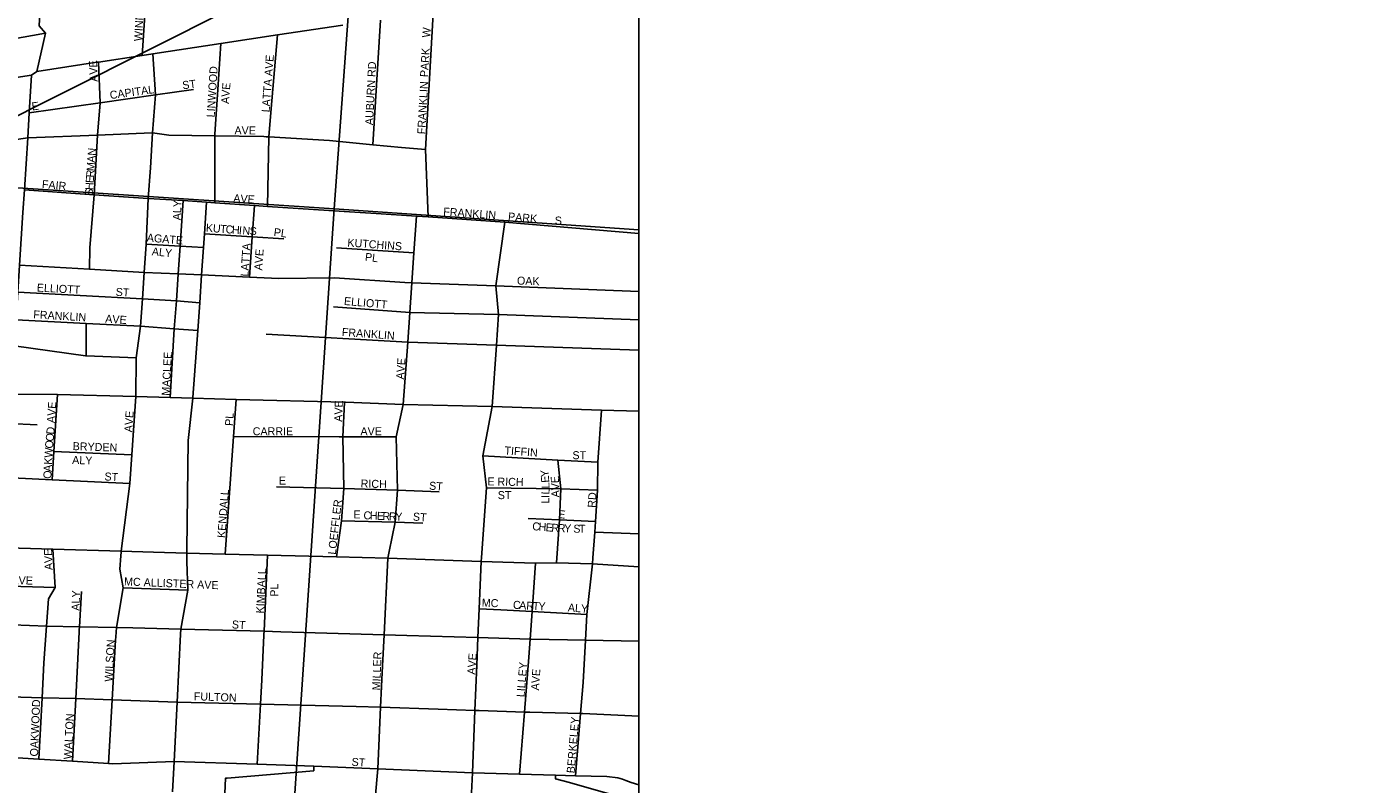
# Model space of a CAD drawing. Extents: x 0 to 34, y -6.2 to 22.
# Drawn here: x 8.351 to 9.927, y 17.461 to 18.357 of the extents above; entities that cross this region are included whole.
import ezdxf

# ---------------------------------------------------------------- set-up
doc = ezdxf.new("R2010")
doc.units = 0
for name, color, linetype in [('GM_X_City_Street', 7, 'Continuous'), ('GM_X_City_Street_Text', 7, 'Continuous'), ('GM_X_Corporation', 7, 'Continuous'), ('GM_X_Interchange_Ramps', 7, 'Continuous'), ('GM_X_Section', 7, 'Continuous'), ('GM_X_US_Route', 7, 'Continuous'), ('SH_Data', 7, 'Continuous')]:
    doc.layers.add(name, color=color, linetype=linetype)

msp = doc.modelspace()

# ---------------------------------------------------------------- linework, layer by layer
at = {"layer": 'GM_X_City_Street'}
for points in [[(8.3631, 18.3042), (8.3734, 18.3494), (8.3659, 18.3582), (8.3692, 18.4197), (8.3729, 18.4904), (8.373, 18.4917)], [(8.4879, 18.3231), (8.4941, 18.4189), (8.4953, 18.4367), (8.4955, 18.4396), (8.4958, 18.4443)], [(8.7608, 18.2175), (8.7699, 18.3648)], [(8.8262, 18.1321), (8.8232, 18.2118), (8.8321, 18.3727)], [(8.2861, 18.3332), (8.3316, 18.342), (8.3734, 18.3494)], [(8.6363, 18.1446), (8.6379, 18.2267), (8.64, 18.2557), (8.6479, 18.3474)], [(8.5737, 18.1488), (8.5737, 18.2279), (8.5738, 18.23), (8.5773, 18.2828), (8.5808, 18.3373)], [(8.4254, 18.0704), (8.426, 18.0957), (8.4311, 18.1584), (8.4352, 18.2289), (8.438, 18.2671), (8.4363, 18.3152)], [(8.4626, 17.7314), (8.463, 17.7356), (8.4631, 17.7367), (8.4734, 17.8167), (8.4756, 17.8508), (8.4805, 17.9197), (8.4806, 17.9653), (8.4859, 18.0028), (8.4882, 18.0351), (8.4903, 18.0666), (8.4925, 18.1), (8.4951, 18.1541), (8.4978, 18.19), (8.5002, 18.2315), (8.5036, 18.2765), (8.5004, 18.325)], [(8.3032, 17.5063), (8.3063, 17.5653), (8.3138, 17.6507), (8.3169, 17.6959), (8.3155, 17.7411), (8.3178, 17.7755), (8.3262, 17.8238), (8.3301, 17.8877), (8.328, 17.9227), (8.3364, 17.9796), (8.3387, 18.0105), (8.3408, 18.043), (8.3428, 18.0751), (8.3466, 18.1374), (8.3485, 18.1642), (8.3525, 18.2258), (8.3542, 18.2554), (8.3569, 18.2998)], [(8.3542, 18.2554), (8.438, 18.2671), (8.5036, 18.2765), (8.5487, 18.2829)], [(8.2737, 18.2141), (8.2764, 18.2145), (8.3525, 18.2258), (8.4352, 18.2289), (8.4992, 18.2314)], [(8.4992, 18.2314), (8.5002, 18.2315), (8.5195, 18.2287), (8.5737, 18.2279), (8.6317, 18.2271), (8.6347, 18.2269), (8.6368, 18.2268)], [(8.6368, 18.2268), (8.6379, 18.2267), (8.7096, 18.2226), (8.7608, 18.2175), (8.7946, 18.2141), (8.8232, 18.2118)], [(8.3485, 18.1642), (8.4311, 18.1584), (8.4951, 18.1541), (8.5364, 18.1514), (8.564, 18.1494), (8.5737, 18.1488), (8.6209, 18.1457), (8.6363, 18.1446), (8.7269, 18.1387), (8.7646, 18.1362), (8.8125, 18.1331)], [(8.5212, 17.9186), (8.5259, 17.9997), (8.5284, 18.0328), (8.5306, 18.0647), (8.5327, 18.0975), (8.5364, 18.1514)], [(8.548, 17.9186), (8.5537, 17.9978), (8.556, 18.0306), (8.5582, 18.0635), (8.5603, 18.0958), (8.5617, 18.1123), (8.564, 18.1494)], [(8.6148, 18.0607), (8.618, 18.1086), (8.6209, 18.1457)], [(8.8125, 18.1331), (8.8095, 18.0897), (8.807, 18.0542), (8.8046, 18.0191), (8.8022, 17.9841), (8.7969, 17.9105), (8.7886, 17.8719), (8.79, 17.8088), (8.7874, 17.7713), (8.7802, 17.7366)], [(8.8125, 18.1331), (8.8262, 18.1321), (8.9169, 18.1261), (9.0755, 18.1125)], [(8.8894, 17.7294), (8.8953, 17.8118), (8.8912, 17.8495), (8.9021, 17.9079), (8.9071, 17.9804), (8.9095, 18.0166), (8.9065, 18.0507), (8.9169, 18.1261)], [(8.5617, 18.1123), (8.618, 18.1086), (8.6556, 18.1064)], [(8.4925, 18.1), (8.5327, 18.0975), (8.5603, 18.0958)], [(8.7178, 18.0957), (8.8095, 18.0897)], [(7.7063, 18.0804), (7.764, 18.0773), (7.8241, 18.0739), (7.8921, 18.0686), (7.953, 18.0647), (8.0271, 18.0618), (8.0864, 18.0573), (8.1478, 18.0538), (8.2018, 18.0505), (8.2656, 18.0473), (8.3408, 18.043), (8.4882, 18.0351), (8.5284, 18.0328), (8.556, 18.0306)], [(8.3428, 18.0751), (8.4254, 18.0704), (8.4903, 18.0666), (8.5306, 18.0647), (8.5582, 18.0635), (8.6148, 18.0607), (8.6497, 18.0593), (8.7155, 18.0601), (8.7986, 18.0547)], [(8.7986, 18.0547), (8.807, 18.0542), (8.9065, 18.0507)], [(8.9065, 18.0507), (9.0755, 18.0438)], [(7.7622, 18.0447), (7.822, 18.041), (7.8901, 18.0366), (7.9508, 18.0329), (8.0249, 18.0288), (8.0839, 18.0254), (8.1454, 18.0219), (8.1993, 18.0186), (8.2634, 18.0144), (8.3387, 18.0105), (8.4217, 18.0062), (8.4859, 18.0028), (8.5259, 17.9997), (8.5537, 17.9978)], [(8.7142, 18.0259), (8.8046, 18.0191), (8.9095, 18.0166), (9.0755, 18.0105)], [(8.4215, 17.968), (8.4217, 18.0062)], [(8.2531, 17.9839), (8.2614, 17.9836), (8.3364, 17.9796), (8.4207, 17.968), (8.421, 17.968)], [(8.6346, 17.9935), (8.8022, 17.9841), (8.9071, 17.9804), (9.0755, 17.9746)], [(8.421, 17.968), (8.4215, 17.968), (8.4806, 17.9653)], [(8.328, 17.9227), (8.3878, 17.922), (8.4805, 17.9197), (8.5212, 17.9186), (8.548, 17.9178), (8.599, 17.9163), (8.7275, 17.913), (8.7285, 17.913), (8.7969, 17.9105), (8.9021, 17.9079), (9.0315, 17.9037), (9.0755, 17.9025)], [(8.3814, 17.8212), (8.3835, 17.8549), (8.3878, 17.922)], [(7.6611, 17.906), (7.8013, 17.9023), (7.8366, 17.901), (7.9008, 17.8997), (7.9745, 17.8937), (8.0127, 17.8935), (8.0535, 17.8924), (8.1008, 17.8908), (8.148, 17.89), (8.1893, 17.889), (8.255, 17.8894), (8.3301, 17.8877), (8.3636, 17.8861)], [(8.5409, 17.7377), (8.5409, 17.7387), (8.5424, 17.8679), (8.548, 17.9178), (8.548, 17.9186)], [(8.5859, 17.7333), (8.5958, 17.8724), (8.599, 17.9163)], [(8.7177, 17.73), (8.7238, 17.7728), (8.7266, 17.8109), (8.7253, 17.872), (8.7275, 17.913)], [(9.0214, 17.729), (9.0235, 17.7595), (9.0243, 17.7721), (9.0269, 17.8091), (9.0272, 17.8421), (9.0315, 17.9037)], [(8.5958, 17.8724), (8.7211, 17.8721)], [(8.7211, 17.8721), (8.7211, 17.8721), (8.7253, 17.872), (8.7886, 17.8719)], [(8.3835, 17.8549), (8.4756, 17.8508)], [(8.8912, 17.8495), (8.9797, 17.8444), (9.0272, 17.8421)], [(8.9782, 17.723), (8.9816, 17.7739), (8.9833, 17.8106), (8.9797, 17.8444)], [(8.0499, 17.835), (8.0968, 17.8333), (8.1443, 17.8315), (8.1838, 17.83), (8.2508, 17.8274), (8.3262, 17.8238), (8.3814, 17.8212), (8.4734, 17.8167)], [(8.6467, 17.8131), (8.7266, 17.8109), (8.79, 17.8088), (8.8393, 17.8071)], [(8.8953, 17.8118), (8.9833, 17.8106), (9.0269, 17.8091)], [(8.7238, 17.7728), (8.7874, 17.7713)], [(8.7874, 17.7713), (8.8202, 17.7701)], [(8.9448, 17.7755), (8.9816, 17.7739)], [(8.9816, 17.7739), (9.0243, 17.7721)], [(9.0235, 17.7595), (9.0755, 17.7574)], [(8.3155, 17.7411), (8.3822, 17.7391), (8.4631, 17.7367), (8.5014, 17.7356), (8.5408, 17.7344), (8.5859, 17.7333), (8.6363, 17.7321), (8.7177, 17.73), (8.7785, 17.7285), (8.8891, 17.7247), (8.9534, 17.7225), (8.9782, 17.723), (9.0209, 17.7217), (9.0755, 17.7184)], [(8.3654, 17.4909), (8.3694, 17.5636), (8.3716, 17.6048), (8.3748, 17.648), (8.3771, 17.6803), (8.3849, 17.6939), (8.3822, 17.7391)], [(8.4565, 17.6316), (8.4567, 17.6356), (8.4574, 17.6465), (8.4654, 17.6935), (8.4614, 17.7157), (8.4626, 17.7314)], [(8.5236, 17.4524), (8.5259, 17.4883), (8.5293, 17.5584), (8.5331, 17.6386), (8.5336, 17.6446), (8.5419, 17.6908), (8.5407, 17.7248), (8.5408, 17.7344), (8.5409, 17.7377)], [(8.6319, 17.6388), (8.6321, 17.6421), (8.6363, 17.7321)], [(8.7802, 17.7366), (8.7785, 17.7285), (8.7742, 17.6381), (8.7724, 17.6013), (8.7701, 17.5523), (8.7666, 17.4793), (8.7638, 17.4443), (8.7611, 17.4091), (8.7547, 17.3346), (8.751, 17.2441), (8.7455, 17.1496)], [(8.8578, 17.1414), (8.865, 17.2366), (8.8676, 17.3283), (8.8742, 17.4053), (8.8773, 17.443), (8.8787, 17.4747), (8.8817, 17.5485), (8.884, 17.602), (8.8853, 17.6347), (8.8868, 17.6688), (8.8891, 17.7247), (8.8894, 17.7294)], [(8.9343, 17.4731), (8.9402, 17.5465), (8.9455, 17.6116), (8.947, 17.6328), (8.9494, 17.6654), (8.9534, 17.7225)], [(9.0006, 17.4713), (9.0067, 17.5449), (9.0098, 17.5816), (9.0126, 17.6316), (9.0143, 17.6618), (9.0209, 17.7217), (9.0214, 17.729)], [(7.9623, 17.7075), (8.0574, 17.7042), (8.1041, 17.7032), (8.191, 17.7001), (8.2422, 17.6983), (8.3169, 17.6959), (8.3849, 17.6939)], [(8.4135, 17.644), (8.4137, 17.6473), (8.4159, 17.6893)], [(8.4654, 17.6935), (8.5419, 17.6908)], [(8.8868, 17.6688), (8.9122, 17.6674), (8.9123, 17.6674)], [(8.9123, 17.6674), (8.9494, 17.6654), (9.0143, 17.6618)], [(8.3138, 17.6507), (8.3748, 17.648), (8.4137, 17.6473), (8.4574, 17.6465), (8.4768, 17.6461), (8.5336, 17.6446), (8.6321, 17.6421), (8.6519, 17.6415), (8.7742, 17.6381), (8.8012, 17.6373), (8.8853, 17.6347), (8.947, 17.6328), (8.9482, 17.6328), (9.0126, 17.6316), (9.0755, 17.6305)], [(8.4053, 17.4884), (8.4092, 17.5625), (8.4133, 17.641), (8.4135, 17.644)], [(8.6241, 17.4851), (8.6279, 17.556), (8.6294, 17.5848), (8.6319, 17.6374), (8.6319, 17.6388)], [(8.448, 17.4857), (8.4524, 17.561), (8.4565, 17.6316)], [(7.8161, 17.5842), (7.8198, 17.5813), (7.8259, 17.5804), (7.8768, 17.5788), (7.9158, 17.579), (7.9363, 17.5783), (7.9533, 17.5777), (8.0365, 17.5738), (8.0978, 17.5727), (8.1285, 17.5715), (8.1636, 17.5695), (8.1825, 17.5685), (8.2335, 17.5669), (8.3063, 17.5653), (8.3694, 17.5636), (8.4092, 17.5625), (8.4524, 17.561), (8.5293, 17.5584), (8.6279, 17.556), (8.7412, 17.5532), (8.7701, 17.5523), (8.8382, 17.5501), (8.8817, 17.5485), (8.8868, 17.5484)], [(8.8868, 17.5484), (8.9402, 17.5465), (8.9415, 17.5464), (8.9435, 17.5463), (8.9468, 17.5463)], [(8.9468, 17.5463), (9.0067, 17.5449), (9.0094, 17.5449), (9.0755, 17.5416)], [(8.2279, 17.5022), (8.2659, 17.4987), (8.3026, 17.4949), (8.3654, 17.4909), (8.4053, 17.4884), (8.448, 17.4857), (8.4533, 17.4854), (8.5259, 17.4883), (8.6241, 17.4851), (8.6912, 17.4824), (8.7666, 17.4793), (8.8787, 17.4747), (8.8793, 17.4747), (8.9343, 17.4731), (8.977, 17.4719), (9.0006, 17.4713), (9.0378, 17.4702), (9.0506, 17.4686), (9.0565, 17.4672), (9.0603, 17.4657), (9.0667, 17.4631), (9.0755, 17.4606)]]:
    msp.add_lwpolyline(points, dxfattribs=at)
at = {"layer": 'GM_X_Corporation'}
msp.add_lwpolyline([(5.4833, 14.3902), (9.0755, 14.3902), (9.0755, 21.1902), (4.181, 21.1902)], dxfattribs=at)
at = {"layer": 'GM_X_Interchange_Ramps'}
for points in [[(8.6912, 17.4824), (8.691, 17.4771), (8.5886, 17.4684), (8.5863, 17.4684), (8.5857, 17.4502)], [(9.044, 17.4325), (9.0449, 17.4488), (9.0253, 17.4541), (8.9935, 17.4631), (8.9769, 17.4677), (8.977, 17.4719)]]:
    msp.add_lwpolyline(points, dxfattribs=at)
at = {"layer": 'GM_X_Section'}
for p, q in [((9.0755, 18.117), (9.0755, 19.1136)), ((9.0755, 17.1279), (9.0755, 18.117))]:
    msp.add_line(p, q, dxfattribs=at)
for points in [[(8.2681, 19.1685), (8.7873, 19.1335), (8.7151, 18.1417), (8.198, 18.176)], [(8.7151, 18.1417), (8.649, 17.1575), (8.1365, 17.1938), (8.198, 18.176)]]:
    msp.add_lwpolyline(points, close=True, dxfattribs=at)
for points in [[(9.0755, 19.1136), (8.7873, 19.1335), (8.7151, 18.1417), (9.0755, 18.117)], [(9.0755, 18.117), (8.7151, 18.1417), (8.649, 17.1575), (9.0755, 17.1279)]]:
    msp.add_lwpolyline(points, dxfattribs=at)
at = {"layer": 'GM_X_US_Route'}
msp.add_lwpolyline([(7.7702, 18.2134), (7.8087, 18.22), (7.8159, 18.2211), (7.8223, 18.2222), (7.8858, 18.2297), (7.9034, 18.2324), (7.9636, 18.2412), (8.0195, 18.2496), (8.0627, 18.2556), (8.0929, 18.2603), (8.1544, 18.2697), (8.1656, 18.2711), (8.2163, 18.2789), (8.2815, 18.2885), (8.3569, 18.2998), (8.3631, 18.3042), (8.4344, 18.315), (8.4363, 18.3152), (8.4879, 18.3231), (8.5004, 18.325), (8.5808, 18.3373), (8.6479, 18.3474), (8.7253, 18.3591)], dxfattribs=at)
at = {"layer": 'SH_Data'}
for points in [[(9.0755, 21.1902), (9.0755, 14.3902), (2.2755, 14.3902), (2.2755, 21.1902)], [(10.0459, 19.9888), (6.7517, 17.4551), (10.0459, 19.1081)]]:
    msp.add_lwpolyline(points, close=True, dxfattribs=at)

# ---------------------------------------------------------------- texts
at = {"layer": 'GM_X_City_Street_Text'}
for s, rotation, p in [('WINNER', 86.9313, (8.4878, 18.3397)), ('W', 85.5871, (8.8286, 18.3439)), ('PARK', 86.3498, (8.8261, 18.2972)), ('AVE', 92.0443, (8.4353, 18.2921)), ('LATTA AVE', 85.659, (8.6386, 18.2556)), ('AUBURN RD', 87.1745, (8.7611, 18.2405)), ('LINWOOD', 86.5309, (8.5736, 18.2497)), ('CAPITAL', 7.7215, (8.4502, 18.2714)), ('ST', 7.5908, (8.536, 18.283)), ('V', 86.3473, (8.5911, 18.2738)), ('E', 84.5286, (8.5917, 18.2821)), ('FRANKLIN', 86.7282, (8.8228, 18.2297)), ('E', 7.1217, (8.3577, 18.258)), ('A', 87.0699, (8.5907, 18.2656)), ('AVE', 0, (8.5971, 18.2297)), ('A', 85.7365, (8.4322, 18.196)), ('N', 85.7365, (8.4328, 18.2043)), ('M', 85.7376, (8.4315, 18.186)), ('FAIR', 354.6467, (8.3689, 18.1664)), ('H', 85.7991, (8.4298, 18.1636)), ('E', 85.7333, (8.4304, 18.1719)), ('R', 85.7223, (8.4309, 18.1785)), ('S', 86.802, (8.4294, 18.157)), ('AVE', 356.0569, (8.5955, 18.1497)), ('ALY', 87.9479, (8.5336, 18.128)), ('FRANKLIN', 355.9166, (8.8439, 18.1339)), ('PARK', 355.1382, (8.9206, 18.1281)), ('S', 0, (8.9762, 18.1231)), ('AGATE', 355.1336, (8.4931, 18.1031)), ('K', 355.7119, (8.563, 18.1147)), ('U', 355.7248, (8.5713, 18.1141)), ('T', 355.7061, (8.5797, 18.1135)), ('C', 355.724, (8.5863, 18.113)), ('H', 355.7119, (8.5938, 18.1124)), ('I', 355.7441, (8.6021, 18.1118)), ('N', 355.7119, (8.6063, 18.1115)), ('S', 357.643, (8.6149, 18.1109)), ('PL', 352.4092, (8.6431, 18.1097)), ('ALY', 354.0977, (8.4989, 18.0869)), ('LATTA', 86.266, (8.6136, 18.0614)), ('AVE', 86.0494, (8.6299, 18.0686)), ('KUTCHINS', 355.9135, (8.7305, 18.0972)), ('PL', 352.8783, (8.7511, 18.0804)), ('OAK', 358.0918, (8.9313, 18.0522)), ('ELLIOTT', 356.985, (8.363, 18.0439)), ('ST', 356.4254, (8.4563, 18.0389)), ('ELLIOTT', 354.9861, (8.7264, 18.0281)), ('FRANKLIN', 356.7313, (8.3588, 18.0122)), ('AVE', 356.0569, (8.4439, 18.0072)), ('FRANKLIN', 355.9135, (8.7239, 17.9914)), ('MACLEE', 86.985, (8.5203, 17.9205)), ('AVE', 86.0569, (8.7978, 17.9397)), ('AVE', 86.0569, (8.3845, 17.8881)), ('AVE', 87.9479, (8.7245, 17.8897)), ('AVE', 86.0494, (8.4761, 17.8772)), ('PL', 86.4254, (8.5953, 17.8847)), ('O', 84.9441, (8.383, 17.8662)), ('D', 84.9697, (8.3837, 17.8745)), ('CARRIE', 0, (8.6187, 17.8739)), ('AVE', 0, (8.7462, 17.8739)), ('W', 86.4331, (8.3816, 17.8471)), ('O', 85.0331, (8.3822, 17.8579)), ('BRYDEN', 357.9915, (8.4055, 17.8564)), ('TIFFIN', 356.0061, (8.9164, 17.8514)), ('K', 87.0431, (8.3811, 17.8389)), ('ALY', 358.0261, (8.4049, 17.8401)), ('ST', 0, (8.9971, 17.8456)), ('O', 87.0481, (8.3803, 17.8222)), ('A', 87.0431, (8.3807, 17.8305)), ('ST', 356.4262, (8.443, 17.8206)), ('E', 0, (8.6496, 17.8156)), ('Y', 93.9377, (8.9692, 17.8248)), ('E', 93.9787, (8.9697, 17.8181)), ('E', 92.7915, (8.9812, 17.8175)), ('KENDALL', 85.6666, (8.5862, 17.7522)), ('RICH', 358.2653, (8.7463, 17.8122)), ('ST', 356.1879, (8.8272, 17.8097)), ('E RICH', 358.7276, (8.8963, 17.8147)), ('L', 88.333, (8.9698, 17.8038)), ('L', 92.0003, (8.97, 17.8111)), ('V', 92.0437, (8.9815, 17.8091)), ('LOEFFLER', 83.5724, (8.717, 17.7324)), ('ST', 0, (8.9087, 17.7984)), ('L', 88.333, (8.9695, 17.793)), ('I', 88.3584, (8.9696, 17.7996)), ('A', 90.5684, (8.9816, 17.8005)), ('RD', 86.989, (9.0246, 17.788)), ('E', 0, (8.7379, 17.7756)), ('C', 357.4735, (8.7496, 17.7747)), ('H', 357.4933, (8.7571, 17.7744)), ('E', 357.4582, (8.7655, 17.774)), ('R', 357.4867, (8.7721, 17.7737)), ('R', 357.9022, (8.7797, 17.7734)), ('Y', 359.5987, (8.7875, 17.7731)), ('ST', 356.1888, (8.808, 17.7731)), ('E', 353.3738, (8.9798, 17.7762)), ('C', 355.3815, (8.9492, 17.7618)), ('H', 355.3756, (8.9567, 17.7612)), ('E', 355.7101, (8.9651, 17.7605)), ('R', 356.487, (8.9719, 17.76)), ('R', 357.1771, (8.9795, 17.7596)), ('Y', 358.0562, (8.9871, 17.7592)), ('S', 358.5248, (8.998, 17.7588)), ('T', 358.5248, (9.0047, 17.7587)), ('AVE', 91.9739, (8.382, 17.7146)), ('KIMBALL', 87.2717, (8.6321, 17.663)), ('AVE', 358.0264, (8.333, 17.6981)), ('MC ALLISTER AVE', 357.6717, (8.4663, 17.6964)), ('ALY', 87.9557, (8.4136, 17.6663)), ('PL', 90, (8.6489, 17.683)), ('MC', 357.3988, (8.8896, 17.6714)), ('C', 355.9403, (8.9264, 17.6689)), ('A', 355.9507, (8.9338, 17.6684)), ('R', 356.2484, (8.9422, 17.6678)), ('T', 357.6181, (8.9499, 17.6673)), ('Y', 358.0112, (8.9567, 17.667)), ('ALY', 355.9166, (8.9914, 17.6656)), ('ST', 356.4262, (8.5938, 17.6456)), ('WILSON', 86.8179, (8.4528, 17.5822)), ('MILLER', 87.8375, (8.7695, 17.5721)), ('AVE', 86.0569, (8.882, 17.5906)), ('LILLEY', 85.3357, (8.9403, 17.5639)), ('AVE', 86.0569, (8.9574, 17.572)), ('OAKWOOD', 87.6451, (8.3645, 17.4939)), ('FULTON', 357.9186, (8.5488, 17.5606)), ('WALTON', 87.1356, (8.4045, 17.4905)), ('BERKELEY', 85.3008, (8.9996, 17.4739)), ('ST', 356.4254, (8.7355, 17.4831))]:
    msp.add_text(s, height=0.00947, rotation=rotation, dxfattribs=at).set_placement(p)

doc.saveas('drawing.dxf')
